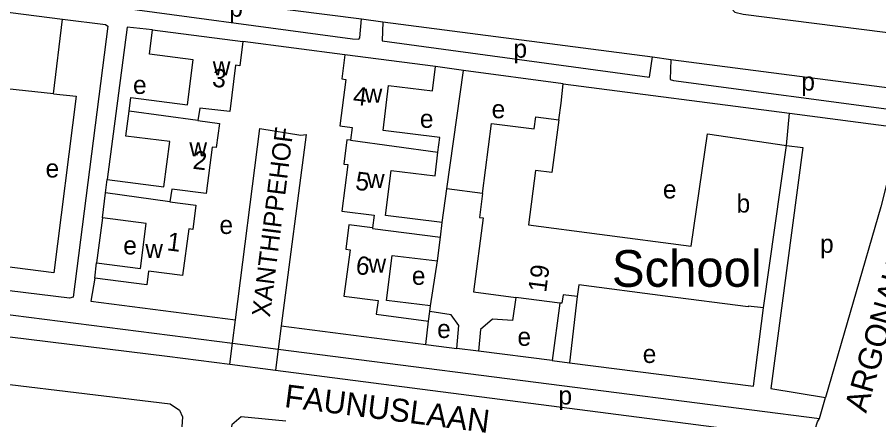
# Model space of a CAD drawing. Extents: x 161773 to 163836, y 384796 to 386521.
# Drawn here: x 162358.6 to 162546.6, y 386036.6 to 386124.5 of the extents above; entities that cross this region are included whole.
import ezdxf

# ---------------------------------------------------------------- set-up
doc = ezdxf.new("R2010")
doc.units = 0
for name, color, linetype in [('BLT_Basislijn', 7, 'Continuous'), ('BLT_Bebouwing', 7, 'Continuous'), ('BLT_Bebouwing_beschrifting', 7, 'Continuous'), ('BLT_Centroide', 7, 'Continuous'), ('BLT_Huisnummer', 7, 'Continuous'), ('BLT_Onderverdeling_panden', 7, 'Continuous'), ('BLT_Straatnaam', 7, 'Continuous'), ('BLT_Straatnaam_verkleind', 7, 'Continuous')]:
    doc.layers.add(name, color=color, linetype=linetype)

msp = doc.modelspace()

# ---------------------------------------------------------------- linework, layer by layer
at = {"layer": 'BLT_Basislijn'}
for p, q in [((162374.45, 386131.66), (162433.75, 386124.08)), ((162331.91, 386128.71), (162368.44, 386124.01)), ((162366.48, 386107.73), (162368.44, 386124.01)), ((162433.75, 386124.08), (162438.39, 386123.47)), ((162438.39, 386123.47), (162497.22, 386115.81)), ((162430.11, 386116.26), (162407.83, 386119.13)), ((162497.22, 386115.81), (162501.28, 386115.25)), ((162455.97, 386112.81), (162449.86, 386113.72)), ((162452.37, 386087.01), (162455.97, 386112.81)), ((162477.78, 386109.92), (162455.97, 386112.81)), ((162477.29, 386105.68), (162477.78, 386109.92)), ((162477.78, 386109.92), (162527.14, 386103.52)), ((162366.48, 386107.73), (162354.02, 386109.11)), ((162476.77, 386102.05), (162477.29, 386105.68)), ((162526.49, 386096.47), (162527.14, 386103.52)), ((162527.14, 386103.52), (162551.47, 386100.36)), ((162451.35, 386079.68), (162452.37, 386087.01)), ((162460.14, 386085.98), (162452.37, 386087.01)), ((162377.18, 386080.67), (162375.92, 386070.85)), ((162250.57, 386073.14), (162405.56, 386053.32)), ((162448.77, 386061.49), (162450.32, 386071.29)), ((162480.81, 386063.5), (162479.14, 386049.06)), ((162476.99, 386062.1), (162475.32, 386049.56)), ((162405.56, 386053.32), (162406.21, 386058.44)), ((162416.21, 386057.15), (162415.55, 386052.04)), ((162416.21, 386057.15), (162447.79, 386053.08)), ((162447.79, 386053.08), (162448.36, 386058.17)), ((162404.97, 386048.73), (162405.56, 386053.32)), ((162405.56, 386053.32), (162415.55, 386052.04)), ((162415.55, 386052.04), (162414.95, 386047.44)), ((162415.55, 386052.04), (162533.72, 386036.93)), ((162459.26, 386051.57), (162454.54, 386052.21)), ((162475.32, 386049.56), (162459.26, 386051.57)), ((162475.32, 386049.56), (162479.14, 386049.06)), ((162404.97, 386048.73), (162414.95, 386047.44)), ((162533.72, 386036.93), (162535.01, 386041.5))]:
    msp.add_line(p, q, dxfattribs=at)
for points in [[(162517.27, 386157.06), (162513.65, 386127.2), (162515.18, 386125.55), (162517.05, 386125.1), (162553.21, 386120.54), (162557.19, 386120.68), (162558.62, 386122.04), (162567.26, 386150.66)], [(162374.45, 386131.66), (162374.52, 386127.46), (162431.78, 386119.74), (162433.18, 386119.69), (162433.34, 386119.94), (162433.75, 386124.08)], [(162368.44, 386124.01), (162377.83, 386122.84), (162378.37, 386122.52), (162370.77, 386063.4), (162369.98, 386063.13), (162340.72, 386066.73)], [(162438.39, 386123.47), (162438.22, 386119.31), (162496.59, 386111.41), (162497.22, 386115.81)], [(162388.1, 386121.68), (162382.55, 386122.26), (162378.25, 386089.03)], [(162501.28, 386115.25), (162501.07, 386110.9), (162501.86, 386110.68), (162552.07, 386103.99)], [(162501.28, 386115.25), (162549.55, 386108.99), (162551.84, 386106.21), (162552.21, 386104.83), (162552.07, 386103.99)], [(162366.48, 386107.73), (162371.43, 386107.21), (162366.61, 386068.7), (162348.88, 386070.92)], [(162406.21, 386058.44), (162411.55, 386100.17), (162420.51, 386098.73), (162421.64, 386098.86), (162416.21, 386057.15)], [(162551.47, 386100.36), (162547.09, 386083.07), (162535.01, 386041.5)], [(162526.49, 386096.47), (162530.08, 386096.04), (162523.07, 386043.45), (162535.01, 386041.5)], [(162375.49, 386067.54), (162374.63, 386062.51), (162406.21, 386058.44)], [(162467.39, 386063.34), (162466.7, 386058.29), (162462.35, 386058.61), (162459.71, 386056.32), (162459.26, 386051.57)], [(162479.14, 386049.06), (162519.31, 386044), (162521.5, 386061.02)], [(162318.39, 386059.45), (162391.31, 386050.49), (162404.97, 386048.73)], [(162454.54, 386052.21), (162454.95, 386057.21), (162453.33, 386059.56), (162448.62, 386060.28)], [(162447.79, 386053.08), (162448.32, 386053.01), (162454.54, 386052.21)], [(162313.11, 385900.9), (162324.65, 386003.69), (162328.7, 386042.76), (162329.67, 386045.91), (162331.52, 386047.14), (162336.37, 386046.82), (162391.99, 386040.11), (162393.98, 386038.7), (162394.67, 386037.26), (162394.3, 386031.81), (162386.9, 385961.46), (162492, 385948), (162502.84, 385946.15), (162504.84, 385944.19), (162504.96, 385941.44), (162504.67, 385940.04), (162487.53, 385882.12)], [(162414.95, 386047.44), (162528.09, 386032.81), (162530, 386032.76), (162531.63, 386033.24), (162532.77, 386034.59), (162533.22, 386036.2), (162533.72, 386036.93)], [(162417.24, 386036.35), (162407.49, 386037.27), (162405.43, 386035.56), (162404.93, 386033.28), (162399.04, 385978.59), (162399.42, 385975.42), (162401.61, 385972.72), (162404.97, 385971.93), (162409.35, 385971.29)]]:
    msp.add_lwpolyline(points, dxfattribs=at)
at = {"layer": 'BLT_Bebouwing'}
for p, q in [((162388.1, 386121.68), (162407.83, 386119.13)), ((162449.86, 386113.72), (162430.11, 386116.26)), ((162377.88, 386086.15), (162378.25, 386089.03)), ((162377.18, 386080.67), (162377.88, 386086.15)), ((162450.95, 386076.47), (162451.35, 386079.68)), ((162450.32, 386071.29), (162450.95, 386076.47)), ((162375.49, 386067.54), (162375.92, 386070.85)), ((162476.99, 386062.1), (162467.39, 386063.34)), ((162448.62, 386060.28), (162448.77, 386061.49)), ((162448.36, 386058.17), (162448.62, 386060.28))]:
    msp.add_line(p, q, dxfattribs=at)
for points in [[(162383, 386103.99), (162383.38, 386106.94), (162395.73, 386105.35), (162396.99, 386115.17), (162387.42, 386116.4), (162388.1, 386121.68)], [(162407.83, 386119.13), (162407.15, 386113.87), (162406.23, 386113.99), (162404.97, 386103.87), (162398.41, 386104.59), (162398.03, 386101.9)], [(162430.11, 386116.26), (162429.43, 386111), (162430.32, 386110.88), (162428.98, 386100.74), (162431.66, 386100.41), (162431.35, 386097.62)], [(162450.4, 386095.05), (162450.79, 386098.23), (162438.42, 386099.74), (162439.62, 386109.57), (162449.21, 386108.4), (162449.86, 386113.72)], [(162378.25, 386089.03), (162390.6, 386087.44), (162391.87, 386097.31), (162382.3, 386098.54), (162383, 386103.99)], [(162460.14, 386085.98), (162462.12, 386101.29), (162471.43, 386100.09), (162471.77, 386102.7), (162476.77, 386102.05)], [(162476.77, 386102.05), (162475.28, 386090.55), (162471.69, 386091.01), (162470.15, 386079.14), (162485.64, 386077.13), (162505.67, 386074.51), (162509.27, 386099), (162526.49, 386096.47)], [(162398.03, 386101.9), (162402.7, 386101.3), (162402.02, 386096.03), (162401.13, 386096.13), (162399.83, 386085.99), (162392.3, 386086.95), (162391.92, 386084.21)], [(162431.35, 386097.62), (162430.53, 386097.72), (162429.86, 386092.42), (162430.77, 386092.31), (162429.44, 386082.16), (162436.47, 386081.27), (162436.12, 386078.53)], [(162521.5, 386061.02), (162526.49, 386096.47)], [(162451.35, 386079.68), (162438.98, 386081.19), (162440.18, 386091.02), (162449.77, 386089.85), (162450.4, 386095.05)], [(162460.14, 386085.98), (162459.47, 386080.77), (162460.27, 386080.67), (162458.18, 386064.53), (162467.39, 386063.34)], [(162391.92, 386084.21), (162397.58, 386083.48), (162396.89, 386078.16), (162396.03, 386078.27), (162394.68, 386068.14), (162387.24, 386069.07), (162386.89, 386066.08), (162375.49, 386067.54)], [(162375.92, 386070.85), (162385.49, 386069.62), (162386.75, 386079.44), (162377.18, 386080.67)], [(162436.12, 386078.53), (162430.98, 386079.18), (162430.3, 386073.88), (162431.22, 386073.74), (162429.9, 386063.61), (162437.33, 386062.64), (162436.9, 386059.65), (162448.36, 386058.17)], [(162448.77, 386061.49), (162439.19, 386062.67), (162440.39, 386072.5), (162450.32, 386071.29)], [(162521.5, 386061.02), (162518.13, 386061.45), (162518.11, 386061.28), (162500, 386063.61), (162481.13, 386066.05), (162480.81, 386063.5)], [(162480.81, 386063.5), (162477.72, 386063.9), (162477.48, 386062.04), (162476.99, 386062.1)]]:
    msp.add_lwpolyline(points, dxfattribs=at)
at = {"layer": 'BLT_Onderverdeling_panden'}
for p, q in [((162398.03, 386101.9), (162383, 386103.99)), ((162431.35, 386097.62), (162450.4, 386095.05)), ((162391.92, 386084.21), (162377.88, 386086.15))]:
    msp.add_line(p, q, dxfattribs=at)
msp.add_lwpolyline([(162436.12, 386078.53), (162436.1, 386078.37), (162450.95, 386076.47)], dxfattribs=at)

# ---------------------------------------------------------------- texts
at = {"layer": 'BLT_Bebouwing_beschrifting'}
msp.add_text('School', height=8, dxfattribs=at).set_placement((162488.38, 386065.64))
at = {"layer": 'BLT_Centroide'}
for s, p in [('p', (162404.88, 386124.57)), ('p', (162466.9, 386115.62)), ('w', (162401.26, 386111.78)), ('p', (162529.73, 386108.45)), ('e', (162383.86, 386107.72)), ('w', (162434.4, 386105.78)), ('e', (162462.13, 386102.41)), ('e', (162446.47, 386100.32)), ('w', (162396.16, 386094.09)), ('e', (162364.77, 386089.49)), ('w', (162434.91, 386087.19)), ('e', (162499.51, 386084.92)), ('b', (162515.59, 386081.84)), ('e', (162402.72, 386077.17)), ('e', (162381.73, 386072.7)), ('p', (162533.82, 386073.05)), ('w', (162386.53, 386071.94)), ('w', (162435.24, 386068.69)), ('e', (162444.72, 386066.08)), ('e', (162450.24, 386054.47)), ('e', (162467.77, 386052.77)), ('e', (162495.11, 386049.02)), ('p', (162476.72, 386039.95))]:
    msp.add_text(s, height=4, dxfattribs=at).set_placement(p)
at = {"layer": 'BLT_Huisnummer'}
for s, rotation, p in [('3', 353.8065, (162401.02, 386109.33)), ('4', 353.0298, (162431.72, 386105.44)), ('2', 352.7805, (162396.77, 386091.42)), ('5', 352.7596, (162432.23, 386086.85)), ('1', 352.8229, (162391.1, 386073.63)), ('6', 352.5613, (162432.32, 386068.48)), ('19', 82.6704, (162474.03, 386064.31))]:
    msp.add_text(s, height=4, rotation=rotation, dxfattribs=at).set_placement(p)
at = {"layer": 'BLT_Straatnaam'}
for s, height, rotation, p in [('ARGONAUTENLAAN', 4.9999, 73.9636, (162543.87, 386037.94)), ('FAUNUSLAAN', 5, 352.7513, (162416.75, 386039.42))]:
    msp.add_text(s, height=height, rotation=rotation, dxfattribs=at).set_placement(p)
at = {"layer": 'BLT_Straatnaam_verkleind'}
msp.add_text('XANTHIPPEHOF', height=4, rotation=82.8796, dxfattribs=at).set_placement((162413.74, 386058.89))

doc.saveas('drawing.dxf')
